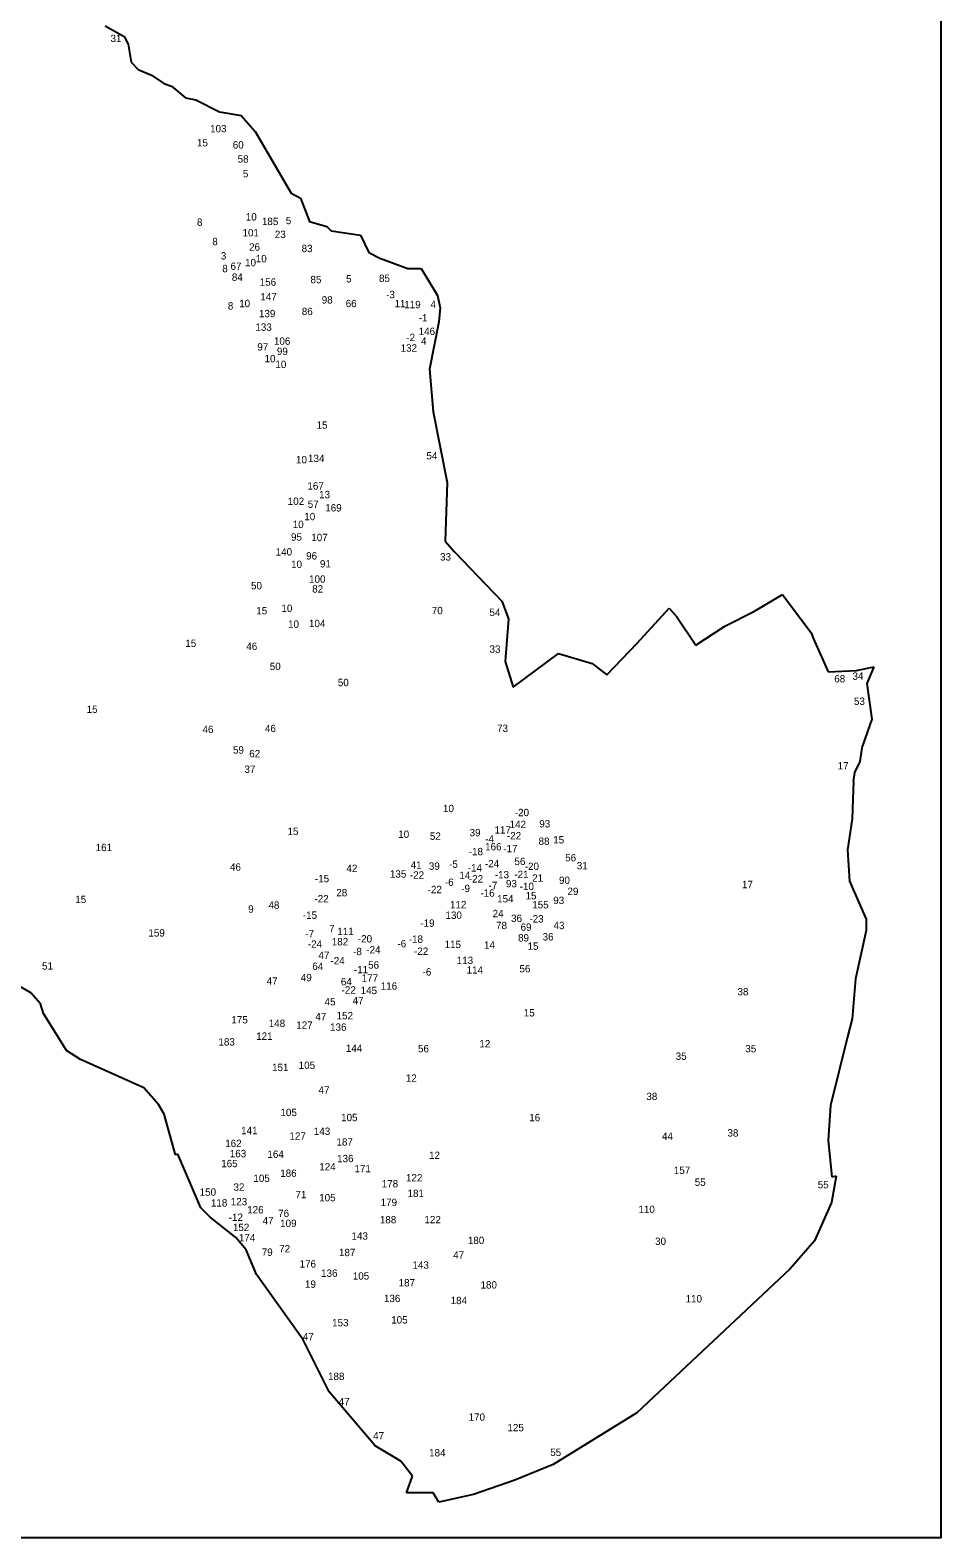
# Model space of a CAD drawing. Extents: x -787023 to -783617, y -975280 to -971607.
# Drawn here: x -784731 to -783617, y -975280 to -973436 of the extents above; entities that cross this region are included whole.
import ezdxf

# ---------------------------------------------------------------- set-up
doc = ezdxf.new("R2010")
doc.units = 0
for name, color, linetype in [('Vrstva 13', 7, 'Continuous'), ('Vrstva 15', 7, 'Continuous'), ('Vrstva 24', 7, 'Continuous')]:
    doc.layers.add(name, color=color, linetype=linetype)

msp = doc.modelspace()

# ---------------------------------------------------------------- linework, layer by layer
at = {"layer": 'Vrstva 13'}
for p, q in [((-784639.2, -973430.8), (-784616, -973443.9)), ((-784616, -973443.9), (-784611.2, -973453.2)), ((-784611.2, -973453.2), (-784607.4, -973475.4)), ((-784607.4, -973475.4), (-784598.8, -973484.2)), ((-784598.8, -973484.2), (-784582.6, -973491.2)), ((-784582.6, -973491.2), (-784567.3, -973501.3)), ((-784567.3, -973501.3), (-784558.1, -973504.6)), ((-784558.1, -973504.6), (-784540.8, -973518.8)), ((-784540.8, -973518.8), (-784528.4, -973521.4)), ((-784528.4, -973521.4), (-784499.1, -973535.9)), ((-784499.1, -973535.9), (-784472.8, -973540.5)), ((-784472.8, -973540.5), (-784455.7, -973560.1)), ((-784455.7, -973560.1), (-784411.7, -973635.6)), ((-784411.7, -973635.6), (-784400, -973641.8)), ((-784400, -973641.8), (-784389.1, -973670.2)), ((-784389.1, -973670.2), (-784367.9, -973676.5)), ((-784367.9, -973676.5), (-784362.8, -973681.8)), ((-784362.8, -973681.8), (-784326.8, -973686.9)), ((-784326.8, -973686.9), (-784316.5, -973708.3))]:
    msp.add_line(p, q, dxfattribs=at)
at = {"layer": 'Vrstva 15'}
for p, q in [((-784316.5, -973708.3), (-784303, -973715)), ((-784303, -973715), (-784268.7, -973727.8)), ((-784268.7, -973727.8), (-784252.6, -973727.8)), ((-784252.6, -973727.8), (-784232.4, -973760.7)), ((-784232.4, -973760.7), (-784229.2, -973775.7)), ((-784229.2, -973775.7), (-784231, -973793)), ((-784231, -973793), (-784242.4, -973850.8)), ((-784242.4, -973850.8), (-784238, -973903.2)), ((-784238, -973903.2), (-784220.8, -973989.3)), ((-784220.8, -973989.3), (-784223.1, -974061.1)), ((-784223.1, -974061.1), (-784212.3, -974074)), ((-784212.3, -974074), (-784153.7, -974134.8)), ((-783844.8, -974146.8), (-783810.3, -974126.6)), ((-783810.3, -974126.6), (-783775.5, -974173.2)), ((-784153.7, -974134.8), (-784145.8, -974156.3)), ((-783988.1, -974185.8), (-783949.1, -974143.1)), ((-783949.1, -974143.1), (-783939.7, -974153.6)), ((-783881.1, -974165.3), (-783844.8, -974146.8)), ((-784145.8, -974156.3), (-784149.6, -974208.5)), ((-783939.7, -974153.6), (-783916.6, -974188.6)), ((-783916.6, -974188.6), (-783881.1, -974165.3)), ((-784025.2, -974224.9), (-783988.1, -974185.8)), ((-783775.5, -974173.2), (-783772.7, -974179.9)), ((-783772.7, -974179.9), (-783754.5, -974220.9)), ((-784140.1, -974239.8), (-784084.6, -974198.5)), ((-784084.6, -974198.5), (-784043.4, -974210.9)), ((-784149.6, -974208.5), (-784140.1, -974239.8)), ((-784043.4, -974210.9), (-784025.2, -974224.9)), ((-783754.5, -974220.9), (-783719.8, -974219.3)), ((-783719.8, -974219.3), (-783698.8, -974215)), ((-783698.8, -974215), (-783707.2, -974235.3)), ((-783707.2, -974235.3), (-783701, -974279)), ((-783701, -974279), (-783712.7, -974311.7)), ((-783715.4, -974330.8), (-783712.7, -974311.7)), ((-783721.8, -974344.2), (-783715.4, -974330.8)), ((-783723.4, -974355.3), (-783721.8, -974344.2)), ((-783723.4, -974355.3), (-783724.3, -974377.3)), ((-783724.3, -974377.3), (-783725, -974401)), ((-783725, -974401), (-783730.7, -974438.9)), ((-783730.7, -974438.9), (-783728.6, -974477.1)), ((-783728.6, -974477.1), (-783707.9, -974523.7)), ((-783707.9, -974523.7), (-783707.9, -974537.5)), ((-783707.9, -974537.5), (-783721.2, -974596.5)), ((-784730.1, -974613.8), (-784758.3, -974597.4)), ((-783721.2, -974596.5), (-783725.1, -974645.3)), ((-784718.3, -974627.2), (-784730.1, -974613.8)), ((-784714.7, -974638.9), (-784718.3, -974627.2)), ((-784686.6, -974684.1), (-784714.7, -974638.9)), ((-783725.1, -974645.3), (-783730.9, -974667.5)), ((-784669.3, -974695.2), (-784686.6, -974684.1)), ((-783730.9, -974667.5), (-783751.7, -974751.5)), ((-784591.8, -974729.7), (-784669.3, -974695.2)), ((-784573.8, -974750.3), (-784591.8, -974729.7)), ((-784566.8, -974762.1), (-784573.8, -974750.3)), ((-783751.7, -974751.5), (-783754.5, -974793.9)), ((-784553, -974811.9), (-784566.8, -974762.1)), ((-783754.5, -974793.9), (-783749.9, -974839)), ((-784550.3, -974811.2), (-784553, -974811.9)), ((-784522, -974876.7), (-784550.3, -974811.2)), ((-783744.6, -974838.1), (-783750.4, -974870.2)), ((-783744.6, -974838.1), (-783749.9, -974839)), ((-784510.9, -974888.3), (-784522, -974876.7)), ((-783750.4, -974870.2), (-783771.4, -974917.1)), ((-784479.4, -974912.8), (-784510.9, -974888.3)), ((-784466.8, -974928), (-784479.4, -974912.8)), ((-783771.4, -974917.1), (-783801, -974951.4)), ((-784454.1, -974958.4), (-784466.8, -974928)), ((-784396.9, -975038), (-784454.1, -974958.4)), ((-783801, -974951.4), (-783988.8, -975127.3)), ((-784365.3, -975101.9), (-784396.9, -975038)), ((-784308.8, -975168), (-784365.3, -975101.9)), ((-783988.8, -975127.3), (-784091, -975190.5)), ((-784277.5, -975186.7), (-784308.8, -975168)), ((-784263.1, -975204.9), (-784277.5, -975186.7)), ((-784091, -975190.5), (-784137.8, -975209.7)), ((-784270.6, -975225.1), (-784263.1, -975204.9)), ((-784137.8, -975209.7), (-784188.4, -975227.2)), ((-784237.9, -975225.3), (-784270.6, -975225.1)), ((-784230.9, -975236.8), (-784237.9, -975225.3)), ((-784188.4, -975227.2), (-784230.9, -975236.8))]:
    msp.add_line(p, q, dxfattribs=at)
msp.add_lwpolyline([(-787022.7, -971607), (-783616.7, -971607), (-783616.7, -975280.4), (-787022.7, -975280.4)], close=True, dxfattribs=at)

# ---------------------------------------------------------------- texts
at = {"layer": 'Vrstva 24'}
for s, p in [('31', (-784632.6, -973450.7)), ('103', (-784510.8, -973561.1)), ('15', (-784526.8, -973578.3)), ('60', (-784483.1, -973581)), ('58', (-784477.1, -973598.2)), ('5', (-784470.7, -973616.2)), ('8', (-784526.9, -973675.5)), ('10', (-784467.1, -973669)), ('185', (-784447.4, -973674.6)), ('5', (-784418.2, -973673.5)), ('101', (-784471.1, -973688.4)), ('23', (-784431.6, -973690.4)), ('8', (-784508.1, -973699.2)), ('3', (-784497.6, -973716.7)), ('26', (-784463.1, -973705.9)), ('83', (-784398.8, -973707.7)), ('8', (-784495.9, -973732.2)), ('67', (-784485.8, -973729.4)), ('10', (-784468, -973725)), ('10', (-784454.9, -973720.1)), ('84', (-784484.2, -973742.8)), ('156', (-784450.1, -973748.7)), ('85', (-784388, -973745.7)), ('5', (-784344.4, -973744.8)), ('85', (-784304.1, -973744.2)), ('147', (-784449.3, -973766.7)), ('98', (-784374.2, -973770.6)), ('-3', (-784295.4, -973764)), ('8', (-784489.1, -973777.9)), ('10', (-784475.2, -973775)), ('139', (-784451, -973787.3)), ('86', (-784398.6, -973784.7)), ('66', (-784344.9, -973775)), ('11', (-784285.1, -973775.1)), ('119', (-784273.2, -973776.3)), ('4', (-784241.1, -973776)), ('133', (-784455.4, -973803.9)), ('-1', (-784255.5, -973792.4)), ('106', (-784432.7, -973821)), ('-2', (-784270.7, -973816.5)), ('146', (-784255.6, -973809)), ('4', (-784252.8, -973821)), ('97', (-784453, -973828.1)), ('10', (-784444.2, -973842.4)), ('99', (-784429.1, -973833.5)), ('132', (-784277.7, -973829.4)), ('10', (-784430.9, -973849.5)), ('15', (-784380.5, -973923.7)), ('10', (-784405.7, -973966)), ('134', (-784391, -973964.5)), ('54', (-784246.1, -973961.2)), ('167', (-784391.7, -973998.1)), ('13', (-784377.4, -974008.7)), ('102', (-784415.8, -974016.9)), ('57', (-784391.3, -974020.5)), ('169', (-784369.9, -974024.9)), ('10', (-784409.7, -974045.2)), ('10', (-784395.5, -974035.6)), ('95', (-784411.8, -974060.6)), ('107', (-784387, -974061.2)), ('140', (-784430.5, -974078.8)), ('96', (-784393.3, -974083.7)), ('33', (-784229.4, -974084.9)), ('10', (-784411.7, -974094)), ('91', (-784376.4, -974093.4)), ('50', (-784460.7, -974120.1)), ('100', (-784389.7, -974112.1)), ('82', (-784385.9, -974124.1)), ('15', (-784454.3, -974150.8)), ('10', (-784423.5, -974147.8)), ('70', (-784239.5, -974150.6)), ('54', (-784169, -974152.8)), ('10', (-784415.4, -974167.2)), ('104', (-784389.8, -974166.4)), ('15', (-784541.1, -974190.6)), ('46', (-784466.5, -974194.4)), ('33', (-784168.9, -974197.7)), ('50', (-784437.8, -974218.9)), ('34', (-783724.8, -974230.8)), ('50', (-784354.5, -974238.6)), ('68', (-783747.1, -974234)), ('53', (-783723, -974261.5)), ('15', (-784661.8, -974271.3)), ('46', (-784520.1, -974295.9)), ('46', (-784443.7, -974294.8)), ('73', (-784159.7, -974294.6)), ('59', (-784482.8, -974321.1)), ('62', (-784462.9, -974325.7)), ('17', (-783742.9, -974340.5)), ('37', (-784468.8, -974344.7)), ('10', (-784225.8, -974392.7)), ('-20', (-784137.9, -974397.6)), ('142', (-784144.3, -974412.1)), ('93', (-784108, -974411.4)), ('15', (-784416.1, -974420.6)), ('10', (-784280.6, -974424.2)), ('52', (-784241.9, -974426.5)), ('39', (-784193.3, -974422.2)), ('-4', (-784174.2, -974430)), ('117', (-784162.8, -974418.9)), ('-22', (-784147.6, -974426)), ('88', (-784108.9, -974432.8)), ('15', (-784091, -974431)), ('161', (-784650.8, -974440.4)), ('-18', (-784194.3, -974445.4)), ('166', (-784174.3, -974439.4)), ('-17', (-784152.1, -974441.7)), ('56', (-784076.3, -974452.9)), ('46', (-784486.5, -974464.3)), ('42', (-784344, -974466)), ('135', (-784290.8, -974472.8)), ('41', (-784265.4, -974461.9)), ('39', (-784243.1, -974463.2)), ('-5', (-784218.3, -974460.8)), ('-14', (-784195.5, -974465.3)), ('-24', (-784174.5, -974460.1)), ('56', (-784138.4, -974457.4)), ('-20', (-784125.8, -974463.4)), ('31', (-784062.1, -974462.7)), ('-15', (-784382.5, -974478.5)), ('-22', (-784266.3, -974474.1)), ('-6', (-784223.5, -974482.9)), ('14', (-784205.8, -974474.5)), ('-9', (-784203.5, -974490.5)), ('-22', (-784194.2, -974478.8)), ('-7', (-784170, -974486.8)), ('-13', (-784162.4, -974473.7)), ('93', (-784148.8, -974484.6)), ('-21', (-784138.5, -974473.3)), ('-10', (-784132, -974488)), ('21', (-784116.7, -974477.7)), ('90', (-784083.9, -974480.5)), ('17', (-783860, -974485.7)), ('15', (-784675.8, -974503.9)), ('-22', (-784383.1, -974503.1)), ('28', (-784356.4, -974495.6)), ('-22', (-784244.6, -974491.8)), ('-16', (-784180, -974496.1)), ('154', (-784159.6, -974503.1)), ('15', (-784124.8, -974499.4)), ('93', (-784090.9, -974505.1)), ('29', (-784073.5, -974494)), ('9', (-784464.2, -974515.7)), ('48', (-784439.4, -974510.9)), ('-15', (-784397.3, -974523.2)), ('130', (-784222.8, -974523.2)), ('112', (-784217.3, -974510.3)), ('24', (-784165.1, -974521.2)), ('36', (-784142.5, -974527.1)), ('-23', (-784120.1, -974527.7)), ('155', (-784116.6, -974510.4)), ('159', (-784586.3, -974544.9)), ('-7', (-784394.3, -974545.7)), ('7', (-784365.2, -974539.7)), ('111', (-784355.1, -974543.1)), ('-19', (-784253.5, -974532.9)), ('78', (-784160.9, -974535.8)), ('69', (-784130.9, -974537.8)), ('43', (-784090.6, -974535.8)), ('-24', (-784391.2, -974558.5)), ('182', (-784361.9, -974555.6)), ('-20', (-784330, -974552.1)), ('-6', (-784281.6, -974558)), ('-18', (-784267.7, -974552.5)), ('115', (-784223.9, -974559)), ('14', (-784175.7, -974559.8)), ('89', (-784134, -974550.9)), ('15', (-784122.4, -974561.1)), ('36', (-784103.9, -974549.7)), ('47', (-784378.2, -974572.3)), ('-24', (-784363.5, -974578.9)), ('-8', (-784335.8, -974567.6)), ('-24', (-784319.7, -974565.5)), ('-22', (-784261.3, -974567.3)), ('113', (-784209, -974578.5)), ('51', (-784716.4, -974585.3)), ('49', (-784399.8, -974599.5)), ('64', (-784385.7, -974585.7)), ('-11', (-784334.8, -974589.8)), ('177', (-784325.3, -974600)), ('56', (-784317.4, -974584.1)), ('-6', (-784250.8, -974592.6)), ('114', (-784196.9, -974590.2)), ('56', (-784132.3, -974588.7)), ('47', (-784441.6, -974603.8)), ('64', (-784350.8, -974604.5)), ('-22', (-784349.9, -974614.7)), ('145', (-784326.6, -974615.3)), ('116', (-784302, -974609.9)), ('38', (-783865.5, -974616.8)), ('45', (-784370.7, -974629)), ('47', (-784336.3, -974627.6)), ('175', (-784484.8, -974651.1)), ('148', (-784439, -974655.5)), ('47', (-784382, -974647.3)), ('152', (-784356, -974646.1)), ('15', (-784127, -974642.6)), ('121', (-784454.4, -974671.2)), ('127', (-784405.4, -974657.7)), ('136', (-784364, -974660.1)), ('183', (-784500.6, -974678.2)), ('144', (-784344.7, -974685.9)), ('56', (-784256.4, -974686.4)), ('12', (-784181.3, -974680.5)), ('35', (-783855.9, -974686.5)), ('151', (-784435, -974709.4)), ('105', (-784402.4, -974706.8)), ('35', (-783941.1, -974695.7)), ('12', (-784271.3, -974722.5)), ('47', (-784378.1, -974737.1)), ('38', (-783977, -974744.9)), ('105', (-784424.7, -974764.5)), ('105', (-784350.5, -974770.7)), ('16', (-784120.3, -974770.8)), ('162', (-784492.3, -974802.4)), ('141', (-784472.8, -974786.6)), ('127', (-784413.7, -974793.3)), ('143', (-784383.9, -974787.5)), ('187', (-784356.2, -974800.6)), ('44', (-783957.9, -974793.6)), ('38', (-783877.8, -974789.5)), ('163', (-784486.7, -974814.8)), ('164', (-784440.7, -974815.6)), ('136', (-784355.4, -974820.9)), ('12', (-784242.9, -974816.9)), ('165', (-784497.2, -974827)), ('186', (-784425, -974838.8)), ('124', (-784377.2, -974830.8)), ('171', (-784334.2, -974833.2)), ('157', (-783943.4, -974835.3)), ('32', (-784482.2, -974855.8)), ('105', (-784457.8, -974845)), ('178', (-784300.8, -974851.7)), ('122', (-784271.1, -974844.4)), ('55', (-783917.8, -974849.8)), ('55', (-783767.3, -974852.8)), ('150', (-784523.6, -974861.9)), ('118', (-784509.8, -974875.1)), ('123', (-784485.5, -974873.6)), ('71', (-784406.4, -974865)), ('105', (-784377.3, -974868.7)), ('179', (-784302.1, -974874.5)), ('181', (-784269.2, -974863.4)), ('-12', (-784488, -974892.7)), ('126', (-784465.4, -974883.6)), ('76', (-784427.5, -974888)), ('188', (-784303.1, -974895.7)), ('122', (-784248.5, -974895.6)), ('110', (-783986.7, -974883)), ('152', (-784482.9, -974905.1)), ('47', (-784446.5, -974896.9)), ('109', (-784425.1, -974900.1)), ('174', (-784475.6, -974917.7)), ('72', (-784426.2, -974931.1)), ('143', (-784337.8, -974915.7)), ('180', (-784195.4, -974921)), ('30', (-783966.3, -974922.1)), ('79', (-784447.6, -974935.4)), ('176', (-784401.3, -974949.8)), ('187', (-784353.1, -974935.8)), ('143', (-784263.2, -974951.1)), ('47', (-784213.4, -974938.9)), ('136', (-784375, -974961.1)), ('105', (-784336.2, -974964.5)), ('19', (-784394.7, -974974.5)), ('187', (-784280.1, -974972.8)), ('180', (-784179.9, -974975.4)), ('136', (-784298.1, -974992)), ('184', (-784216.5, -974994.5)), ('110', (-783929, -974992.4)), ('153', (-784361.5, -975021.6)), ('105', (-784289.2, -975018.2)), ('47', (-784397.3, -975038.6)), ('188', (-784366.5, -975087.3)), ('47', (-784353.4, -975118.2)), ('170', (-784194.5, -975137.1)), ('125', (-784147, -975150)), ('47', (-784311.3, -975160)), ('184', (-784242.8, -975180.8)), ('55', (-784094.6, -975180.3))]:
    msp.add_text(s, height=9, dxfattribs=at).set_placement(p)

doc.saveas('drawing.dxf')
